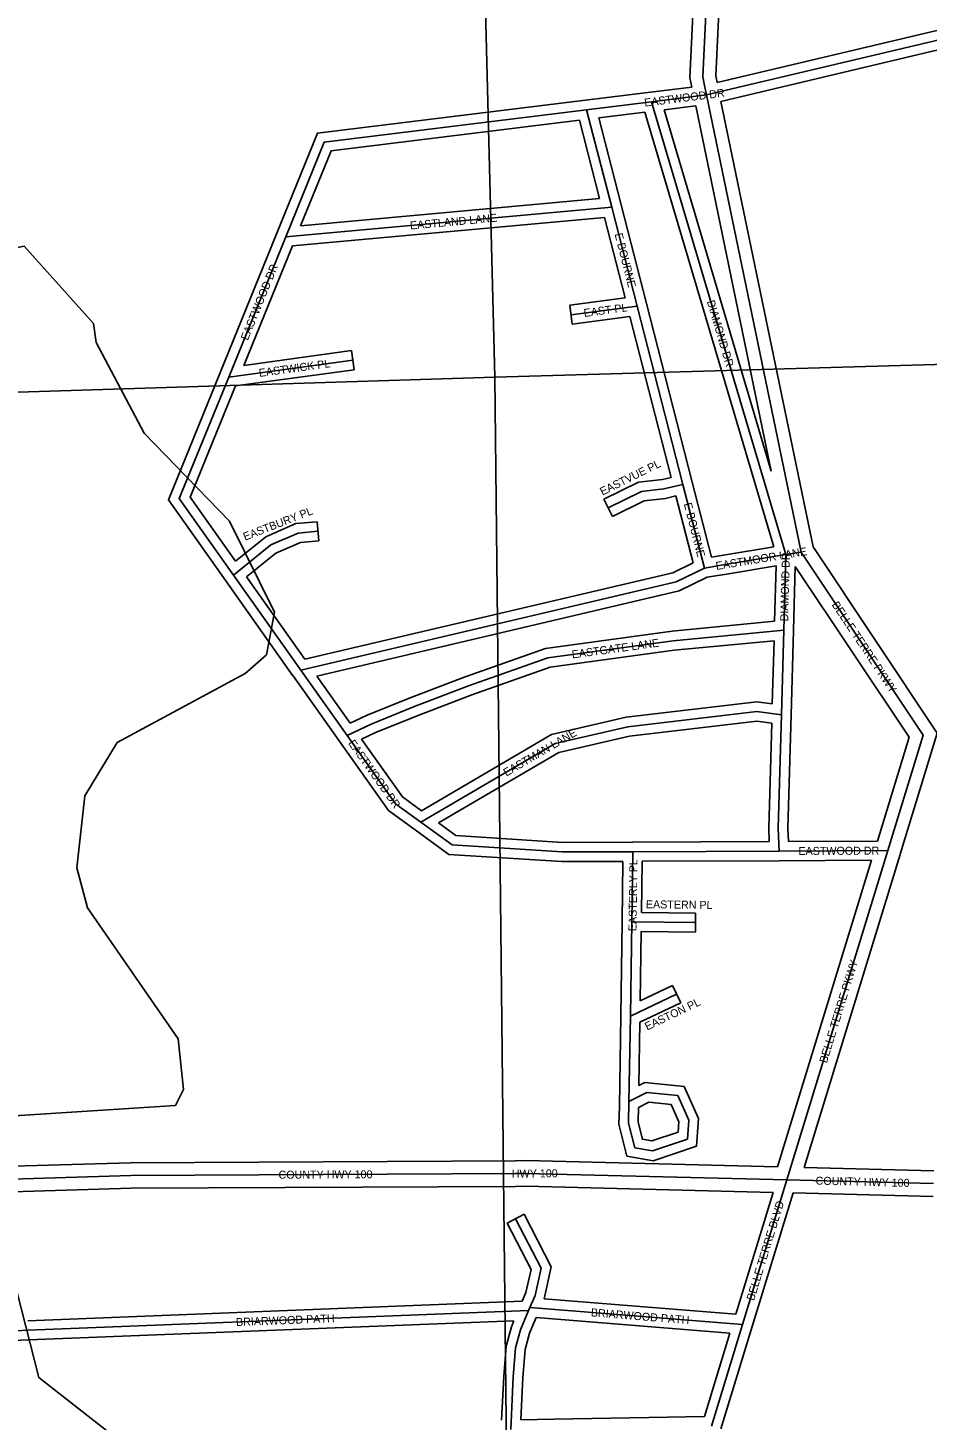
# Model space of a CAD drawing. Extents: x 457167 to 656239, y 1787309 to 1969297.
# Drawn here: x 583625 to 586434, y 1868606 to 1872956 of the extents above; entities that cross this region are included whole.
import ezdxf

# ---------------------------------------------------------------- set-up
doc = ezdxf.new("R2010")
doc.units = 0
for name, color, linetype in [('Level 1', 7, 'Continuous'), ('Level 22', 7, 'Continuous'), ('Level 23', 7, 'Continuous'), ('Level 31', 7, 'Continuous'), ('Level 32', 7, 'Continuous'), ('Level 34', 7, 'Continuous'), ('Level 5', 7, 'Continuous'), ('Level 7', 7, 'Continuous')]:
    doc.layers.add(name, color=color, linetype=linetype)

msp = doc.modelspace()

# ---------------------------------------------------------------- linework, layer by layer
at = {"layer": 'Level 1'}
for p, q in [((584949.895, 1877168.15), (585083.45, 1871864.58)), ((590281.277, 1872016.794), (585083.45, 1871864.58)), ((585083.45, 1871864.58), (580077.699, 1871707.169)), ((585083.45, 1871864.58), (585141.066, 1866577.511))]:
    msp.add_line(p, q, dxfattribs=at)
at = {"layer": 'Level 22'}
for p, q in [((585738.973, 1872776.818), (585745.28, 1872746.989)), ((585745.28, 1872746.989), (586040.394, 1871318.806)), ((586311.643, 1870385.939), (585996.281, 1869357.088)), ((585148.313, 1869376.882), (585181.088, 1869377.184)), ((585996.281, 1869357.088), (585181.088, 1869377.184)), ((586454.15, 1869345.681), (585996.281, 1869357.088))]:
    msp.add_line(p, q, dxfattribs=at)
for points in [[(585887.869, 1874622.341), (585782.325, 1873826.546), (585733.614, 1872803.011), (585738.973, 1872776.818)], [(586040.394, 1871318.806), (586421.777, 1870746.456), (586311.643, 1870385.939)], [(583506.358, 1869357.516), (583947.093, 1869370.837), (585148.313, 1869376.882)]]:
    msp.add_lwpolyline(points, dxfattribs=at)
at = {"layer": 'Level 23'}
for p, q in [((585711.555, 1872712.528), (585947.43, 1871571.024)), ((585790.291, 1872726.833), (586077.995, 1871334.514)), ((586260.539, 1870355.706), (585966.93, 1869397.824)), ((586349.887, 1870374.216), (586049.974, 1869395.762)), ((585147.946, 1869416.881), (585181.398, 1869417.187)), ((585966.931, 1869397.824), (585181.399, 1869417.188)), ((586455.147, 1869385.668), (586049.974, 1869395.763)), ((585148.681, 1869336.884), (585180.78, 1869337.178)), ((585952.974, 1869318.142), (585180.779, 1869337.177)), ((586453.155, 1869305.691), (586015.255, 1869316.601))]:
    msp.add_line(p, q, dxfattribs=at)
for points in [[(585848.215, 1874627.6), (585742.45, 1873830.133), (585693.42, 1872799.904), (585699.24, 1872771.455)], [(585927.521, 1874617.081), (585822.199, 1873822.96), (585773.807, 1872806.117), (585778.009, 1872785.586)], [(586077.995, 1871334.514), (586465.565, 1870752.878), (586349.899, 1870374.252)], [(586022.281, 1871273.852), (586377.99, 1870740.032), (586278.938, 1870415.791)], [(583505.149, 1869397.499), (583946.387, 1869410.835), (585148.112, 1869416.882)], [(583507.566, 1869317.534), (583947.798, 1869330.84), (585148.515, 1869336.883)]]:
    msp.add_lwpolyline(points, dxfattribs=at)
at = {"layer": 'Level 31'}
for p, q in [((585745.28, 1872746.989), (585573.745, 1872725.497)), ((585573.745, 1872725.497), (585370.704, 1872700.793)), ((585573.745, 1872725.497), (585993.288, 1871310.894)), ((585370.704, 1872700.793), (585449.03, 1872396.282)), ((584431.01, 1872303.329), (585449.03, 1872396.282)), ((585449.03, 1872396.282), (585528.305, 1872087.407)), ((584431.01, 1872303.329), (584252.937, 1871865.131)), ((585528.305, 1872087.407), (585322.075, 1872060.164)), ((585528.305, 1872087.407), (585671.382, 1871529.685)), ((584252.937, 1871865.131), (584640.264, 1871918.2)), ((585671.382, 1871529.685), (585738.343, 1871268.832)), ((585993.288, 1871310.894), (586040.394, 1871318.806)), ((585993.288, 1871310.894), (585986.797, 1871074.909)), ((584267.967, 1871246.562), (584478.034, 1870949.795)), ((585986.797, 1871074.909), (585979.614, 1870809.833)), ((584478.034, 1870949.795), (584622.735, 1870745.881)), ((585514.565, 1870382.356), (585511.602, 1870163.091)), ((585514.565, 1870382.356), (585971.81, 1870384.398)), ((585971.81, 1870384.398), (586311.643, 1870385.939)), ((585511.602, 1870163.091), (585507.542, 1869868.92)), ((585511.602, 1870163.091), (585710.787, 1870160.895)), ((585507.542, 1869868.92), (585651.816, 1869937.736)), ((585507.542, 1869868.92), (585502.58, 1869601.59)), ((585996.281, 1869357.088), (585857.885, 1868905.328)), ((583626.675, 1868887.103), (585189.498, 1868948.808)), ((585193.623, 1868958.637), (585189.498, 1868948.808)), ((585193.623, 1868958.637), (585857.885, 1868905.328)), ((582957.113, 1868857.51), (583626.675, 1868887.103)), ((585857.885, 1868905.328), (585760.629, 1868588.087))]:
    msp.add_line(p, q, dxfattribs=at)
for points in [[(585745.28, 1872746.989), (587034.764, 1873052.925), (587600.408, 1873192.237), (588507.108, 1873323.662), (589520.564, 1873553.826), (589799.232, 1873528.963), (590281.133, 1873461.923)], [(585370.704, 1872700.793), (584551.215, 1872599.821), (584431.01, 1872303.329)], [(584252.937, 1871865.131), (584098.52, 1871485.797), (584267.967, 1871246.562)], [(585671.382, 1871529.685), (585612.174, 1871515.979), (585541.522, 1871508.113), (585438.015, 1871456.675)], [(584267.967, 1871246.562), (584384.287, 1871340.881), (584469.633, 1871378.171), (584531.37, 1871383.506)], [(584478.034, 1870949.795), (585649.805, 1871225.728), (585738.343, 1871268.832)], [(585738.343, 1871268.832), (585802.955, 1871279.619), (585993.288, 1871310.894)], [(584622.735, 1870745.881), (584697.259, 1870781.373), (584830.047, 1870835.299), (585001.357, 1870900.424), (585249.393, 1870988.311), (585640.865, 1871041.746), (585986.797, 1871074.909)], [(584852.902, 1870474.894), (585272.11, 1870720.27), (585499.08, 1870772.928), (585901.995, 1870820.162), (585979.614, 1870809.833)], [(585979.614, 1870809.833), (585969.4, 1870456.038), (585971.81, 1870384.398)], [(584622.735, 1870745.881), (584773.782, 1870532.136), (584852.902, 1870474.894)], [(584852.902, 1870474.894), (584951.086, 1870403.434), (585294.055, 1870381.686), (585514.565, 1870382.356)], [(585502.58, 1869601.59), (585501.497, 1869534.32), (585520.761, 1869457.556), (585576.429, 1869447.996), (585685.64, 1869484.516), (585689.57, 1869543.416), (585655.35, 1869620.572)], [(585655.35, 1869620.572), (585558.638, 1869630.573), (585502.58, 1869601.59)], [(585148.68, 1869235.793), (585228.573, 1869081.459), (585209.635, 1868996.406), (585193.623, 1868958.637)], [(585189.498, 1868948.808), (585164.244, 1868888.13), (585148.865, 1868832.523), (585141.689, 1868741.266), (585133.42, 1868576.919)]]:
    msp.add_lwpolyline(points, dxfattribs=at)
at = {"layer": 'Level 32'}
for p, q in [((585570.015, 1872755.264), (585367.08, 1872730.573)), ((585699.24, 1872771.455), (585570.015, 1872755.264)), ((585711.556, 1872712.528), (585612.562, 1872700.125)), ((585348.215, 1872667.794), (585411.194, 1872422.952)), ((585552.194, 1872692.652), (585408.278, 1872675.142)), ((585408.279, 1872675.142), (585478.085, 1872403.755)), ((585552.194, 1872692.653), (585954.853, 1871334.981)), ((585612.563, 1872700.124), (585947.43, 1871571.024)), ((584477.31, 1872337.681), (585411.194, 1872422.951)), ((585478.089, 1872403.74), (585557.365, 1872094.865)), ((584451.927, 1872275.113), (585426.323, 1872364.083)), ((585426.323, 1872364.082), (585490.837, 1872112.717)), ((584403.216, 1872314.623), (584225.145, 1871876.426)), ((584451.927, 1872275.113), (584300.262, 1871901.895)), ((585490.837, 1872112.717), (585318.146, 1872089.906)), ((585557.365, 1872094.861), (585700.441, 1871537.139)), ((585326.004, 1872030.422), (585318.146, 1872089.906)), ((585505.858, 1872054.18), (585326.004, 1872030.422)), ((585505.859, 1872054.18), (585634.69, 1871551.984)), ((584300.262, 1871901.895), (584636.192, 1871947.922)), ((584636.192, 1871947.922), (584644.336, 1871888.477)), ((584274.188, 1871837.762), (584644.336, 1871888.477)), ((585700.44, 1871537.143), (585760.557, 1871302.956)), ((585649.609, 1871493.85), (585703.198, 1871285.088)), ((585451.366, 1871429.808), (585424.664, 1871483.541)), ((584528.787, 1871413.395), (584533.953, 1871353.616)), ((585962.3, 1871275.399), (585957.538, 1871102.241)), ((586022.281, 1871273.852), (586016.786, 1871074.083)), ((584243.481, 1871229.229), (584453.548, 1870932.461)), ((584308.69, 1871240.957), (584490.839, 1870983.631)), ((586016.786, 1871074.096), (586009.604, 1870809.021)), ((585955.89, 1871041.807), (585950.528, 1870843.968)), ((584453.568, 1870932.432), (584598.269, 1870728.519)), ((584528.294, 1870930.808), (584632.606, 1870783.81)), ((585514.43, 1870412.356), (585940.789, 1870414.259)), ((586000.815, 1870414.529), (586278.937, 1870415.79)), ((585544.165, 1870352.486), (585971.945, 1870354.397)), ((585971.947, 1870354.397), (586260.539, 1870355.706)), ((585484.155, 1870352.262), (585481.605, 1870163.496)), ((585544.165, 1870352.486), (585542.006, 1870192.758)), ((585542.007, 1870192.757), (585711.119, 1870190.893)), ((585711.119, 1870190.893), (585710.456, 1870130.896)), ((585481.605, 1870163.506), (585477.545, 1869869.334)), ((585541.187, 1870132.761), (585538.207, 1869916.784)), ((585541.187, 1870132.761), (585710.456, 1870130.896)), ((585538.207, 1869916.784), (585638.901, 1869964.814)), ((585638.901, 1869964.814), (585664.733, 1869910.657)), ((585537.254, 1869849.851), (585664.733, 1869910.657)), ((585477.546, 1869869.382), (585473.191, 1869586.847)), ((585537.253, 1869849.851), (585534.199, 1869651.711)), ((585952.975, 1869318.142), (585836.261, 1868937.161)), ((586015.255, 1869316.601), (585883.126, 1868885.3)), ((585175.321, 1869249.585), (585122.037, 1869222.001)), ((583625.491, 1868917.08), (585169.26, 1868978.031)), ((585237.872, 1868985.182), (585836.261, 1868937.161)), ((585212.914, 1868926.992), (585818.258, 1868878.411)), ((583628, 1868857.132), (585143.756, 1868916.977)), ((585818.258, 1868878.411), (585738.323, 1868617.677)), ((585883.125, 1868885.294), (585789.312, 1868579.293)), ((583030.645, 1868830.73), (583628, 1868857.132)), ((585268.131, 1868609.201), (585564.711, 1868614.454)), ((585564.685, 1868614.453), (585738.322, 1868617.677)), ((585164.995, 1868607.456), (585268.155, 1868609.201))]:
    msp.add_line(p, q, dxfattribs=at)
for points in [[(585778.009, 1872785.586), (587027.714, 1873082.086), (587594.655, 1873221.718), (588501.625, 1873353.182), (589518.525, 1873584.127), (589802.634, 1873558.779), (590251.392, 1873496.349)], [(585790.291, 1872726.834), (587041.815, 1873023.765), (587606.161, 1873162.757), (588512.591, 1873294.143), (589522.603, 1873523.525), (589795.83, 1873499.146), (590251.663, 1873435.732)], [(585367.035, 1872730.568), (584530.039, 1872627.441), (584403.207, 1872314.601)], [(585348.215, 1872667.794), (584572.39, 1872572.203), (584477.31, 1872337.681)], [(584225.151, 1871876.442), (584064.535, 1871481.877), (584243.485, 1871229.223)], [(584274.188, 1871837.761), (584132.507, 1871489.718), (584273.943, 1871290.031)], [(585634.69, 1871551.984), (585607.115, 1871545.601), (585532.926, 1871537.342), (585424.664, 1871483.541)], [(585649.609, 1871493.85), (585617.234, 1871486.356), (585550.119, 1871478.885), (585451.366, 1871429.808)], [(584273.943, 1871290.03), (584368.55, 1871366.746), (584462.138, 1871407.635), (584528.787, 1871413.395)], [(584308.69, 1871240.958), (584400.025, 1871315.018), (584477.127, 1871348.706), (584533.953, 1871353.616)], [(585760.557, 1871302.956), (585798.052, 1871309.216), (585954.853, 1871334.981)], [(584490.84, 1870983.631), (585639.676, 1871254.164), (585703.197, 1871285.087)], [(585747.569, 1871239.956), (585807.856, 1871250.021), (585962.3, 1871275.399)], [(584528.294, 1870930.808), (585659.934, 1871197.291), (585747.57, 1871239.956)], [(584632.606, 1870783.811), (584685.155, 1870808.838), (584819.071, 1870863.221), (584991.016, 1870928.588), (585242.28, 1871017.62), (585637.403, 1871071.553), (585957.537, 1871102.241)], [(584667.79, 1870734.108), (584709.364, 1870753.909), (584841.022, 1870807.376), (585011.698, 1870872.261), (585256.506, 1870959.004), (585644.327, 1871011.941), (585955.89, 1871041.807)], [(584854.635, 1870510.67), (585260.889, 1870748.464), (585493.926, 1870802.53), (585902.23, 1870850.396), (585950.528, 1870843.968)], [(584907.631, 1870472.166), (585283.331, 1870692.076), (585504.232, 1870743.326), (585901.76, 1870789.928), (585948.847, 1870783.662)], [(586009.602, 1870808.968), (585999.415, 1870456.11), (586000.815, 1870414.529)], [(585948.847, 1870783.662), (585939.385, 1870455.966), (585940.789, 1870414.259)], [(584598.269, 1870728.519), (584752.159, 1870510.752), (584835.317, 1870450.588)], [(584667.79, 1870734.107), (584795.405, 1870553.521), (584854.635, 1870510.669)], [(584835.248, 1870450.638), (584940.484, 1870374.046), (585293.15, 1870351.683), (585484.155, 1870352.262)], [(584907.631, 1870472.166), (584961.689, 1870432.821), (585294.96, 1870411.689), (585514.473, 1870412.356)], [(585675.728, 1869648.625), (585552.815, 1869661.336), (585534.199, 1869651.711)], [(585473.191, 1869586.847), (585471.436, 1869530.851), (585496.42, 1869431.297), (585578.787, 1869417.151), (585714.234, 1869462.443), (585719.997, 1869548.809), (585675.728, 1869648.625)], [(585532.289, 1869583.176), (585531.557, 1869537.789), (585545.102, 1869483.816), (585574.07, 1869478.841), (585657.045, 1869506.587), (585659.143, 1869538.023), (585634.975, 1869592.517)], [(585634.975, 1869592.517), (585564.46, 1869599.811), (585532.288, 1869583.175)], [(585175.321, 1869249.585), (585260.224, 1869085.575), (585237.872, 1868985.182)], [(585122.037, 1869222.001), (585196.921, 1869077.344), (585180.947, 1869005.596), (585169.26, 1868978.031)], [(585212.914, 1868926.992), (585192.66, 1868878.329), (585178.546, 1868827.301), (585171.63, 1868739.336), (585164.995, 1868607.457)], [(585143.756, 1868916.977), (585135.828, 1868897.931), (585119.182, 1868837.746), (585111.748, 1868743.196), (585104.867, 1868606.427)]]:
    msp.add_lwpolyline(points, dxfattribs=at)
at = {"layer": 'Level 5'}
msp.add_lwpolyline([(584925.352, 1866987.635), (584559.113, 1867513.211), (584317.975, 1868097.008), (584193.161, 1868322.221), (583660.06, 1868739.595), (583452.531, 1869548.436)], dxfattribs=at)
at = {"layer": 'Level 7'}
msp.add_lwpolyline([(583452.531, 1869548.436), (584086.13, 1869589.47), (584111.2, 1869639.451), (584094.688, 1869797.843), (583811.68, 1870206.647), (583778.469, 1870331.729), (583803.698, 1870556.773), (583903.928, 1870723.396), (584304.301, 1870939.721), (584371.052, 1870997.972), (584396.191, 1871131.355), (584254.777, 1871414.918), (583988.3, 1871690.311), (583838.546, 1871973.905), (583830.275, 1872032.266), (583613.79, 1872274.238), (583447.029, 1872241.096), (583413.659, 1872207.786), (583430.2, 1872099.374), (583480.121, 1871999.273), (583488.292, 1871849.221)], dxfattribs=at)

# ---------------------------------------------------------------- texts
at = {"layer": 'Level 34'}
for s, height, rotation, p in [('EASTWOOD DR', 25, 7.141175, (585552.31, 1872710.214)), ('EASTLAND LANE', 25, 5.216817, (584820.242, 1872326.317)), ('E BOURNE', 25, 284.394161, (585457.769, 1872311.954)), ('EASTWOOD DR', 25, 67.883978, (584312.288, 1871977.983)), ('EAST PL', 25, 7.524839, (585363.129, 1872052.979)), ('DIAMOND DR', 25, 286.518892, (585745.741, 1872101.606)), ('EASTWICK PL', 25, 7.801414, (584348.599, 1871865.622)), ('EASTVUE PL', 25, 26.425092, (585419.971, 1871494.751)), ('EASTBURY PL', 25, 21.365492, (584303.6, 1871353.771)), ('E BOURNE', 25, 284.396447, (585673.96, 1871469.367)), ('EASTMOOR LANE', 25, 9.331161, (585776.141, 1871262.546)), ('DIAMOND DR', 25, 88.423928, (586000.042, 1871101.883)), ('BELLE TERRE PKWY', 25, 303.676981, (586135.018, 1871154.261)), ('EASTGATE LANE', 25, 7.772439, (585326.05, 1870986.16)), ('EASTMAN LANE', 25, 30.341483, (585119.684, 1870616.667)), ('EASTWOOD DR', 25, 305.247561, (584624.795, 1870721.306)), ('EASTWOOD DR', 25, 0.259442, (586032.178, 1870372.172)), ('EASTERLY PL', 25, 89.225494, (585526.296, 1870134.144)), ('EASTERN PL', 25, 359.367803, (585555.76, 1870205.791)), ('BELLE TERRE PKWY', 25, 72.958258, (586120.638, 1869720.145)), ('EASTON PL', 25, 25.499922, (585559.532, 1869823.402)), ('COUNTY HWY 100', 25, 0.288061, (584408.397, 1869360.66)), ('HWY 100', 25, 0.525758, (585137.336, 1869363.923)), ('COUNTY HWY 100', 24.99916, 358.572433, (586085.583, 1869342.361)), ('BELLE TERRE BLVD', 25, 72.967217, (585893.169, 1868977.828)), ('BRIARWOOD PATH', 24.99916, 2.260739, (584275.932, 1868900.229)), ('BRIARWOOD PATH', 25, 355.411414, (585383.093, 1868930.892))]:
    msp.add_text(s, height=height, rotation=rotation, dxfattribs=at).set_placement(p)

doc.saveas('drawing.dxf')
